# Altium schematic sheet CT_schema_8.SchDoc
size 250 x 169 mm
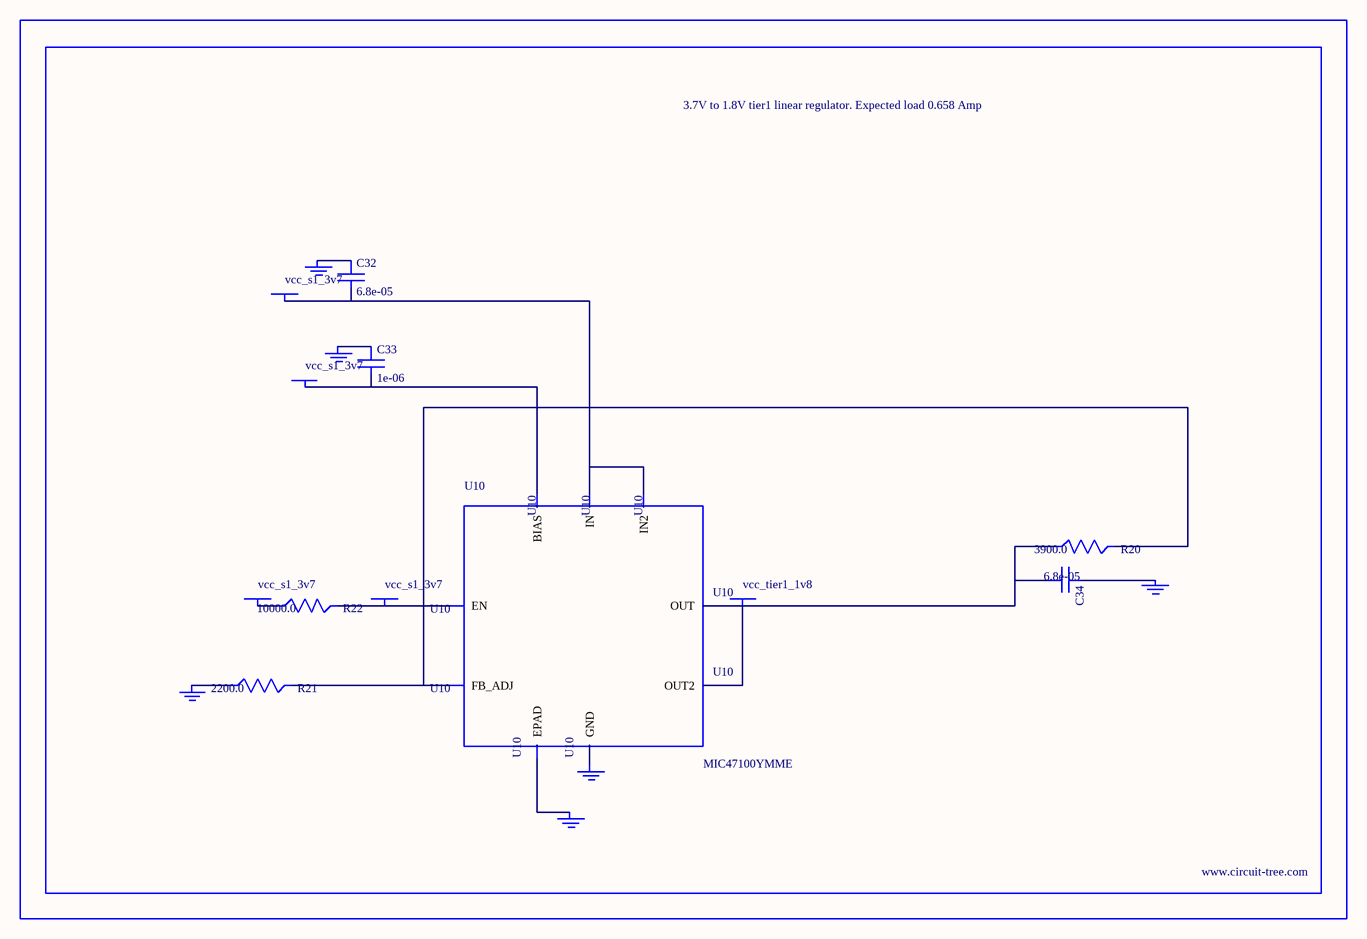
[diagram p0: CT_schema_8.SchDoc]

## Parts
BORDER7  (no value)
C32  6.8e-05  [2220]
C33  1e-06  [C0603]
C34  6.8e-05  [2220]
GND_INSTANCE_7_0  (no value)
GND_INSTANCE_7_1  (no value)
GND_INSTANCE_7_2  (no value)
GND_INSTANCE_7_3  (no value)
GND_INSTANCE_7_4  (no value)
GND_INSTANCE_7_5  (no value)
POWER_INSTANCE_7_0  vcc_s1_3v7
POWER_INSTANCE_7_1  vcc_s1_3v7
POWER_INSTANCE_7_2  vcc_s1_3v7
POWER_INSTANCE_7_3  vcc_s1_3v7
POWER_INSTANCE_7_4  vcc_tier1_1v8
R20  3900.0  [R0603]
R21  2200.0  [R0603]
R22  10000.0  [R0603]
U10  MIC47100YMME  [MSOP-8_EP]

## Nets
NetC32_1: C32.1 GND_INSTANCE_7_0.0(GND)
NetC32_2: C32.2 POWER_INSTANCE_7_0.0(PWR) U10.1(IN) U10.2(IN2)
NetC33_1: C33.1 GND_INSTANCE_7_1.0(GND)
NetC33_2: C33.2 POWER_INSTANCE_7_1.0(PWR) U10.4(BIAS)
NetC34_1: C34.1 GND_INSTANCE_7_3.0(GND)
NetC34_2: C34.2 POWER_INSTANCE_7_4.0(PWR) R20.1 U10.7(OUT) U10.8(OUT2)
NetGND_INSTANCE_7_2_0: GND_INSTANCE_7_2.0(GND) R21.1
NetGND_INSTANCE_7_4_0: GND_INSTANCE_7_4.0(GND) U10.EPAD
NetGND_INSTANCE_7_5_0: GND_INSTANCE_7_5.0(GND) U10.3(GND)
NetPOWER_INSTANCE_7_2_0: POWER_INSTANCE_7_2.0(PWR) R22.1
NetPOWER_INSTANCE_7_3_0: POWER_INSTANCE_7_3.0(PWR) R22.2 U10.5(EN)
NetR20_2: R20.2 R21.2 U10.6(FB_ADJ)

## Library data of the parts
BORDER7 = BORDER_PAGE7
C32 C34 = C5750X5R1A686M
C33 = C0603C105K3RACTU
GND_INSTANCE_7_0-GND_INSTANCE_7_5 = GND
POWER_INSTANCE_7_0-POWER_INSTANCE_7_4 = PWR
R20 = RC0603JR-073K9L
R21 = RC0603JR-072K2L
R22 = RC0603JR-0710KL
